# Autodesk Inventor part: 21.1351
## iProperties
Created: 2006-12
Part Number: 21.1351
Document SubType Name: Modeling
Designer: Andy Moles
Material: Steel, Mild
Mass: 3.99144 g
Surface Area: 5.54975 cm^2
Volume: 0.507817 cm^3
Density: 7.86 g/cm^3
Description: M8 SQUARE NUT
Vendor: S
Author: Andy Moles
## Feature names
1. Extrusion1
2. Revolution1
